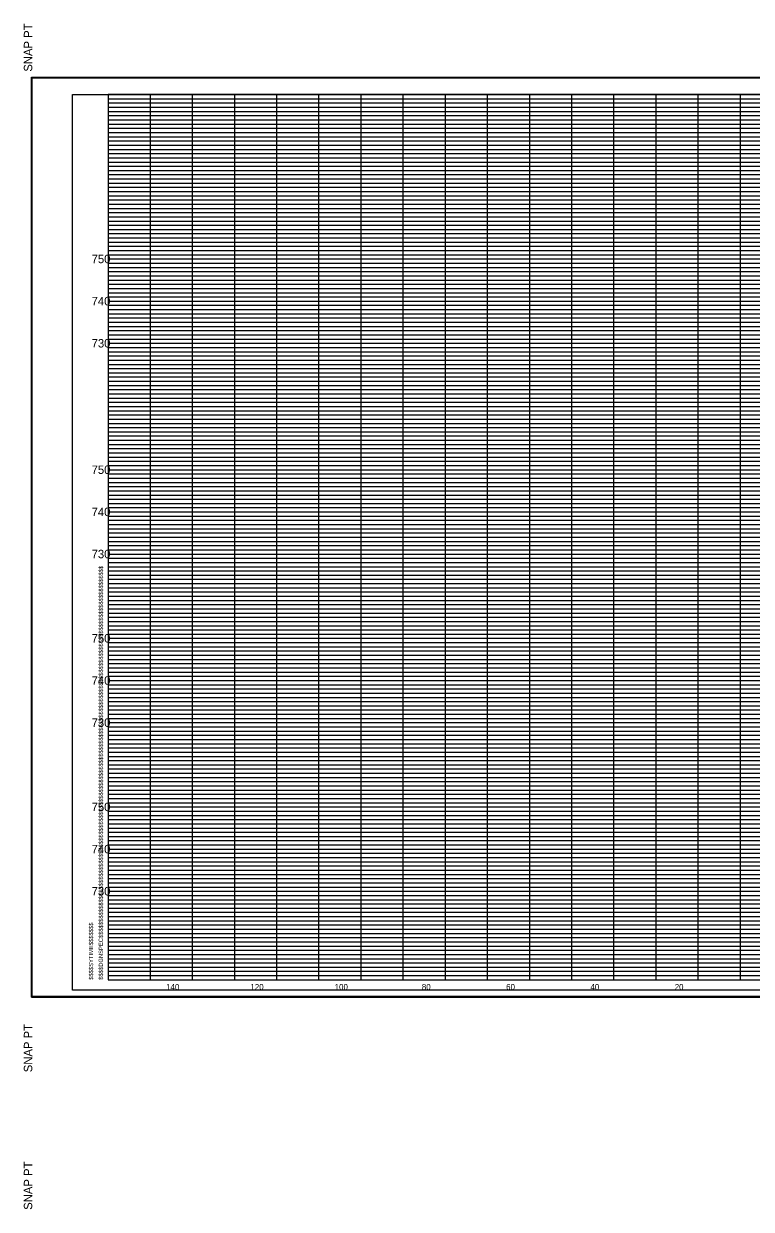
# Model space of a CAD drawing. Extents: x -200 to 1704, y -325 to 2307.
# Drawn here: x 979.9 to 1152.6, y 2025.5 to 2306.8 of the extents above; entities that cross this region are included whole.
import ezdxf

# ---------------------------------------------------------------- set-up
doc = ezdxf.new("R2010")
doc.units = 0
for name, color, linetype in [('DESIGN - SHEET - Corner Text', 7, 'Continuous'), ('DESIGN - SHEET - Light Grid', 7, 'Continuous'), ('DESIGN - SHEET - Linework', 7, 'Continuous'), ('DESIGN - SHEET - Plot Shape', 7, 'Continuous'), ('DESIGN - TYPICAL - Text', 7, 'Continuous')]:
    doc.layers.add(name, color=color, linetype=linetype)

msp = doc.modelspace()

# ---------------------------------------------------------------- linework, layer by layer
at = {"layer": 'DESIGN - SHEET - Light Grid'}
for p, q in [((1000, 2289), (1080, 2289)), ((1000, 2288), (1080, 2288)), ((1000, 2287), (1080, 2287)), ((1080, 2289), (1160, 2289)), ((1080, 2288), (1160, 2288)), ((1080, 2287), (1160, 2287)), ((1000, 2286), (1080, 2286)), ((1000, 2285), (1080, 2285)), ((1000, 2284), (1080, 2284)), ((1080, 2286), (1160, 2286)), ((1080, 2285), (1160, 2285)), ((1080, 2284), (1160, 2284)), ((1000, 2283), (1080, 2283)), ((1000, 2282), (1080, 2282)), ((1080, 2283), (1160, 2283)), ((1080, 2282), (1160, 2282)), ((1000, 2281), (1080, 2281)), ((1000, 2279), (1080, 2279)), ((1080, 2281), (1160, 2281)), ((1080, 2279), (1160, 2279)), ((1000, 2278), (1080, 2278)), ((1000, 2277), (1080, 2277)), ((1000, 2276), (1080, 2276)), ((1080, 2278), (1160, 2278)), ((1080, 2277), (1160, 2277)), ((1080, 2276), (1160, 2276)), ((1000, 2275), (1080, 2275)), ((1000, 2274), (1080, 2274)), ((1000, 2273), (1080, 2273)), ((1080, 2275), (1160, 2275)), ((1080, 2274), (1160, 2274)), ((1080, 2273), (1160, 2273)), ((1000, 2272), (1080, 2272)), ((1000, 2271), (1080, 2271)), ((1080, 2272), (1160, 2272)), ((1080, 2271), (1160, 2271)), ((1000, 2269), (1080, 2269)), ((1000, 2268), (1080, 2268)), ((1000, 2267), (1080, 2267)), ((1080, 2269), (1160, 2269)), ((1080, 2268), (1160, 2268)), ((1080, 2267), (1160, 2267)), ((1000, 2266), (1080, 2266)), ((1000, 2265), (1080, 2265)), ((1080, 2266), (1160, 2266)), ((1080, 2265), (1160, 2265)), ((1000, 2264), (1080, 2264)), ((1000, 2263), (1080, 2263)), ((1000, 2262), (1080, 2262)), ((1080, 2264), (1160, 2264)), ((1080, 2263), (1160, 2263)), ((1080, 2262), (1160, 2262)), ((1000, 2261), (1080, 2261)), ((1000, 2259), (1080, 2259)), ((1080, 2261), (1160, 2261)), ((1080, 2259), (1160, 2259)), ((1000, 2258), (1080, 2258)), ((1000, 2257), (1080, 2257)), ((1000, 2256), (1080, 2256)), ((1080, 2258), (1160, 2258)), ((1080, 2257), (1160, 2257)), ((1080, 2256), (1160, 2256)), ((1000, 2255), (1080, 2255)), ((1000, 2254), (1080, 2254)), ((1000, 2253), (1080, 2253)), ((1080, 2255), (1160, 2255)), ((1080, 2254), (1160, 2254)), ((1080, 2253), (1160, 2253)), ((1000, 2252), (1080, 2252)), ((1000, 2251), (1080, 2251)), ((1080, 2252), (1160, 2252)), ((1080, 2251), (1160, 2251)), ((1000, 2249), (1080, 2249)), ((1000, 2248), (1080, 2248)), ((1080, 2249), (1160, 2249)), ((1080, 2248), (1160, 2248)), ((1000, 2247), (1080, 2247)), ((1000, 2246), (1080, 2246)), ((1000, 2245), (1080, 2245)), ((1080, 2247), (1160, 2247)), ((1080, 2246), (1160, 2246)), ((1080, 2245), (1160, 2245)), ((1000, 2244), (1080, 2244)), ((1000, 2243), (1080, 2243)), ((1000, 2242), (1080, 2242)), ((1080, 2244), (1160, 2244)), ((1080, 2243), (1160, 2243)), ((1080, 2242), (1160, 2242)), ((1000, 2241), (1080, 2241)), ((1000, 2239), (1080, 2239)), ((1080, 2241), (1160, 2241)), ((1080, 2239), (1160, 2239)), ((1000, 2238), (1080, 2238)), ((1000, 2237), (1080, 2237)), ((1080, 2238), (1160, 2238)), ((1080, 2237), (1160, 2237)), ((1000, 2236), (1080, 2236)), ((1000, 2235), (1080, 2235)), ((1000, 2234), (1080, 2234)), ((1080, 2236), (1160, 2236)), ((1080, 2235), (1160, 2235)), ((1080, 2234), (1160, 2234)), ((1000, 2233), (1080, 2233)), ((1000, 2232), (1080, 2232)), ((1000, 2231), (1080, 2231)), ((1080, 2233), (1160, 2233)), ((1080, 2232), (1160, 2232)), ((1080, 2231), (1160, 2231)), ((1000, 2229), (1080, 2229)), ((1000, 2228), (1080, 2228)), ((1080, 2229), (1160, 2229)), ((1080, 2228), (1160, 2228)), ((1000, 2227), (1080, 2227)), ((1000, 2226), (1080, 2226)), ((1000, 2225), (1080, 2225)), ((1080, 2227), (1160, 2227)), ((1080, 2226), (1160, 2226)), ((1080, 2225), (1160, 2225)), ((1000, 2224), (1080, 2224)), ((1000, 2223), (1080, 2223)), ((1000, 2222), (1080, 2222)), ((1080, 2224), (1160, 2224)), ((1080, 2223), (1160, 2223)), ((1080, 2222), (1160, 2222)), ((1000, 2221), (1080, 2221)), ((1080, 2221), (1160, 2221)), ((1000, 2219), (1080, 2219)), ((1000, 2218), (1080, 2218)), ((1000, 2217), (1080, 2217)), ((1080, 2219), (1160, 2219)), ((1080, 2218), (1160, 2218)), ((1080, 2217), (1160, 2217)), ((1000, 2216), (1080, 2216)), ((1000, 2215), (1080, 2215)), ((1000, 2214), (1080, 2214)), ((1080, 2216), (1160, 2216)), ((1080, 2215), (1160, 2215)), ((1080, 2214), (1160, 2214)), ((1000, 2213), (1080, 2213)), ((1000, 2212), (1080, 2212)), ((1000, 2211), (1080, 2211)), ((1080, 2213), (1160, 2213)), ((1080, 2212), (1160, 2212)), ((1080, 2211), (1160, 2211)), ((1000, 2209), (1080, 2209)), ((1000, 2208), (1080, 2208)), ((1080, 2209), (1160, 2209)), ((1080, 2208), (1160, 2208)), ((1000, 2207), (1080, 2207)), ((1000, 2206), (1080, 2206)), ((1080, 2207), (1160, 2207)), ((1080, 2206), (1160, 2206)), ((1000, 2205), (1080, 2205)), ((1000, 2204), (1080, 2204)), ((1000, 2203), (1080, 2203)), ((1080, 2205), (1160, 2205)), ((1080, 2204), (1160, 2204)), ((1080, 2203), (1160, 2203)), ((1000, 2202), (1080, 2202)), ((1000, 2201), (1080, 2201)), ((1080, 2202), (1160, 2202)), ((1080, 2201), (1160, 2201)), ((1000, 2199), (1080, 2199)), ((1000, 2198), (1080, 2198)), ((1000, 2197), (1080, 2197)), ((1080, 2199), (1160, 2199)), ((1080, 2198), (1160, 2198)), ((1080, 2197), (1160, 2197)), ((1000, 2196), (1080, 2196)), ((1000, 2195), (1080, 2195)), ((1000, 2194), (1080, 2194)), ((1080, 2196), (1160, 2196)), ((1080, 2195), (1160, 2195)), ((1080, 2194), (1160, 2194)), ((1000, 2193), (1080, 2193)), ((1000, 2192), (1080, 2192)), ((1080, 2193), (1160, 2193)), ((1080, 2192), (1160, 2192)), ((1000, 2191), (1080, 2191)), ((1000, 2189), (1080, 2189)), ((1080, 2191), (1160, 2191)), ((1080, 2189), (1160, 2189)), ((1000, 2188), (1080, 2188)), ((1000, 2187), (1080, 2187)), ((1000, 2186), (1080, 2186)), ((1080, 2188), (1160, 2188)), ((1080, 2187), (1160, 2187)), ((1080, 2186), (1160, 2186)), ((1000, 2185), (1080, 2185)), ((1000, 2184), (1080, 2184)), ((1000, 2183), (1080, 2183)), ((1080, 2185), (1160, 2185)), ((1080, 2184), (1160, 2184)), ((1080, 2183), (1160, 2183)), ((1000, 2182), (1080, 2182)), ((1000, 2181), (1080, 2181)), ((1080, 2182), (1160, 2182)), ((1080, 2181), (1160, 2181)), ((1000, 2179), (1080, 2179)), ((1000, 2178), (1080, 2178)), ((1000, 2177), (1080, 2177)), ((1080, 2179), (1160, 2179)), ((1080, 2178), (1160, 2178)), ((1080, 2177), (1160, 2177)), ((1000, 2176), (1080, 2176)), ((1000, 2175), (1080, 2175)), ((1080, 2176), (1160, 2176)), ((1080, 2175), (1160, 2175)), ((1000, 2174), (1080, 2174)), ((1000, 2173), (1080, 2173)), ((1000, 2172), (1080, 2172)), ((1080, 2174), (1160, 2174)), ((1080, 2173), (1160, 2173)), ((1080, 2172), (1160, 2172)), ((1000, 2171), (1080, 2171)), ((1000, 2169), (1080, 2169)), ((1080, 2171), (1160, 2171)), ((1080, 2169), (1160, 2169)), ((1000, 2168), (1080, 2168)), ((1000, 2167), (1080, 2167)), ((1000, 2166), (1080, 2166)), ((1080, 2168), (1160, 2168)), ((1080, 2167), (1160, 2167)), ((1080, 2166), (1160, 2166)), ((1000, 2165), (1080, 2165)), ((1000, 2164), (1080, 2164)), ((1000, 2163), (1080, 2163)), ((1080, 2165), (1160, 2165)), ((1080, 2164), (1160, 2164)), ((1080, 2163), (1160, 2163)), ((1000, 2162), (1080, 2162)), ((1000, 2161), (1080, 2161)), ((1080, 2162), (1160, 2162)), ((1080, 2161), (1160, 2161)), ((1000, 2159), (1080, 2159)), ((1000, 2158), (1080, 2158)), ((1080, 2159), (1160, 2159)), ((1080, 2158), (1160, 2158)), ((1000, 2157), (1080, 2157)), ((1000, 2156), (1080, 2156)), ((1000, 2155), (1080, 2155)), ((1080, 2157), (1160, 2157)), ((1080, 2156), (1160, 2156)), ((1080, 2155), (1160, 2155)), ((1000, 2154), (1080, 2154)), ((1000, 2153), (1080, 2153)), ((1000, 2152), (1080, 2152)), ((1080, 2154), (1160, 2154)), ((1080, 2153), (1160, 2153)), ((1080, 2152), (1160, 2152)), ((1000, 2151), (1080, 2151)), ((1000, 2149), (1080, 2149)), ((1080, 2151), (1160, 2151)), ((1080, 2149), (1160, 2149)), ((1000, 2148), (1080, 2148)), ((1000, 2147), (1080, 2147)), ((1080, 2148), (1160, 2148)), ((1080, 2147), (1160, 2147)), ((1000, 2146), (1080, 2146)), ((1000, 2145), (1080, 2145)), ((1000, 2144), (1080, 2144)), ((1080, 2146), (1160, 2146)), ((1080, 2145), (1160, 2145)), ((1080, 2144), (1160, 2144)), ((1000, 2143), (1080, 2143)), ((1000, 2142), (1080, 2142)), ((1000, 2141), (1080, 2141)), ((1080, 2143), (1160, 2143)), ((1080, 2142), (1160, 2142)), ((1080, 2141), (1160, 2141)), ((1000, 2139), (1080, 2139)), ((1000, 2138), (1080, 2138)), ((1080, 2139), (1160, 2139)), ((1080, 2138), (1160, 2138)), ((1000, 2137), (1080, 2137)), ((1000, 2136), (1080, 2136)), ((1000, 2135), (1080, 2135)), ((1080, 2137), (1160, 2137)), ((1080, 2136), (1160, 2136)), ((1080, 2135), (1160, 2135)), ((1000, 2134), (1080, 2134)), ((1000, 2133), (1080, 2133)), ((1000, 2132), (1080, 2132)), ((1080, 2134), (1160, 2134)), ((1080, 2133), (1160, 2133)), ((1080, 2132), (1160, 2132)), ((1000, 2131), (1080, 2131)), ((1080, 2131), (1160, 2131)), ((1000, 2129), (1080, 2129)), ((1000, 2128), (1080, 2128)), ((1000, 2127), (1080, 2127)), ((1080, 2129), (1160, 2129)), ((1080, 2128), (1160, 2128)), ((1080, 2127), (1160, 2127)), ((1000, 2126), (1080, 2126)), ((1000, 2125), (1080, 2125)), ((1000, 2124), (1080, 2124)), ((1080, 2126), (1160, 2126)), ((1080, 2125), (1160, 2125)), ((1080, 2124), (1160, 2124)), ((1000, 2123), (1080, 2123)), ((1000, 2122), (1080, 2122)), ((1000, 2121), (1080, 2121)), ((1080, 2123), (1160, 2123)), ((1080, 2122), (1160, 2122)), ((1080, 2121), (1160, 2121)), ((1000, 2119), (1080, 2119)), ((1000, 2118), (1080, 2118)), ((1080, 2119), (1160, 2119)), ((1080, 2118), (1160, 2118)), ((1000, 2117), (1080, 2117)), ((1000, 2116), (1080, 2116)), ((1080, 2117), (1160, 2117)), ((1080, 2116), (1160, 2116)), ((1000, 2115), (1080, 2115)), ((1000, 2114), (1080, 2114)), ((1000, 2113), (1080, 2113)), ((1080, 2115), (1160, 2115)), ((1080, 2114), (1160, 2114)), ((1080, 2113), (1160, 2113)), ((1000, 2112), (1080, 2112)), ((1000, 2111), (1080, 2111)), ((1080, 2112), (1160, 2112)), ((1080, 2111), (1160, 2111)), ((1000, 2109), (1080, 2109)), ((1000, 2108), (1080, 2108)), ((1000, 2107), (1080, 2107)), ((1080, 2109), (1160, 2109)), ((1080, 2108), (1160, 2108)), ((1080, 2107), (1160, 2107)), ((1000, 2106), (1080, 2106)), ((1000, 2105), (1080, 2105)), ((1000, 2104), (1080, 2104)), ((1080, 2106), (1160, 2106)), ((1080, 2105), (1160, 2105)), ((1080, 2104), (1160, 2104)), ((1000, 2103), (1080, 2103)), ((1000, 2102), (1080, 2102)), ((1080, 2103), (1160, 2103)), ((1080, 2102), (1160, 2102)), ((1000, 2101), (1080, 2101)), ((1000, 2099), (1080, 2099)), ((1080, 2101), (1160, 2101)), ((1080, 2099), (1160, 2099)), ((1000, 2098), (1080, 2098)), ((1000, 2097), (1080, 2097)), ((1000, 2096), (1080, 2096)), ((1080, 2098), (1160, 2098)), ((1080, 2097), (1160, 2097)), ((1080, 2096), (1160, 2096)), ((1000, 2095), (1080, 2095)), ((1000, 2094), (1080, 2094)), ((1000, 2093), (1080, 2093)), ((1080, 2095), (1160, 2095)), ((1080, 2094), (1160, 2094)), ((1080, 2093), (1160, 2093)), ((1000, 2092), (1080, 2092)), ((1000, 2091), (1080, 2091)), ((1080, 2092), (1160, 2092)), ((1080, 2091), (1160, 2091)), ((1000, 2089), (1080, 2089)), ((1000, 2088), (1080, 2088)), ((1000, 2087), (1080, 2087)), ((1080, 2089), (1160, 2089)), ((1080, 2088), (1160, 2088)), ((1080, 2087), (1160, 2087)), ((1000, 2086), (1080, 2086)), ((1000, 2085), (1080, 2085)), ((1080, 2086), (1160, 2086)), ((1080, 2085), (1160, 2085)), ((1000, 2084), (1080, 2084)), ((1000, 2083), (1080, 2083)), ((1000, 2082), (1080, 2082)), ((1080, 2084), (1160, 2084)), ((1080, 2083), (1160, 2083)), ((1080, 2082), (1160, 2082)), ((1000, 2081), (1080, 2081)), ((1080, 2081), (1160, 2081))]:
    msp.add_line(p, q, dxfattribs=at)
at = {"layer": 'DESIGN - SHEET - Linework'}
for p, q in [((981.77, 2075.86), (981.77, 2294.14)), ((981.77, 2294.14), (1322.17, 2294.14)), ((1010, 2080), (1010, 2290)), ((1020, 2080), (1020, 2290)), ((1030, 2080), (1030, 2290)), ((1040, 2080), (1040, 2290)), ((1050, 2080), (1050, 2290)), ((1060, 2080), (1060, 2290)), ((1070, 2080), (1070, 2290)), ((1080, 2080), (1080, 2290)), ((1090, 2080), (1090, 2290)), ((1100, 2080), (1100, 2290)), ((1110, 2080), (1110, 2290)), ((1120, 2080), (1120, 2290)), ((1130, 2080), (1130, 2290)), ((1140, 2080), (1140, 2290)), ((1150, 2080), (1150, 2290)), ((1000, 2280), (1280, 2280)), ((1000, 2270), (1320, 2270)), ((1000, 2260), (1320, 2260)), ((1000, 2250), (1320, 2250)), ((1000, 2240), (1320, 2240)), ((1000, 2230), (1320, 2230)), ((1000, 2220), (1320, 2220)), ((1000, 2210), (1320, 2210)), ((1000, 2200), (1320, 2200)), ((1000, 2190), (1320, 2190)), ((1000, 2180), (1320, 2180)), ((1000, 2170), (1320, 2170)), ((1000, 2160), (1320, 2160)), ((1000, 2150), (1320, 2150)), ((1000, 2140), (1320, 2140)), ((1000, 2130), (1320, 2130)), ((1000, 2120), (1320, 2120)), ((1000, 2110), (1320, 2110)), ((1000, 2100), (1320, 2100)), ((1000, 2090), (1320, 2090)), ((981.77, 2075.86), (1322.17, 2075.86))]:
    msp.add_line(p, q, dxfattribs=at)
msp.add_lwpolyline([(1000, 2290), (1000, 2080), (1320, 2080), (1320, 2290), (1000, 2290)], dxfattribs=at)
at = {"layer": 'DESIGN - SHEET - Plot Shape'}
for points in [[(981.97, 2293.94), (1321.97, 2293.94), (1321.97, 2076.06), (981.97, 2076.06)], [(991.5, 2290), (1320, 2290), (1320, 2077.5), (991.5, 2077.5)]]:
    msp.add_lwpolyline(points, close=True, dxfattribs=at)

# ---------------------------------------------------------------- texts
at = {"layer": 'DESIGN - SHEET - Corner Text'}
for s, height, p in [('  SNAP PT', 2, (981.97, 2293.94)), ('$$$$DGNSPEC$$$$$$$$$$$$$$$$$$$$$$$$$$$$$$$$$$$$$$$$$$$$$$$$$$$$$$$$$$$$$$$$$$$$$$$$$$$$$$$$$$$$$$$$$$$$$$$$$$$$$$$$$$$$$$$$$$$', 1.00002, (998.74, 2080)), ('$$$$SYTIME$$$$$$$', 1, (996.42, 2080)), ('SNAP PT  ', 2, (981.97, 2058.06)), ('  SNAP PT', 2, (981.97, 2023.94))]:
    msp.add_text(s, height=height, rotation=90, dxfattribs=at).set_placement(p)
at = {"layer": 'DESIGN - TYPICAL - Text'}
for s, height, p in [('     750     ', 2, (992.34, 2250)), ('     740     ', 2, (992.34, 2240)), ('     730     ', 2, (992.34, 2230)), ('     750     ', 2, (992.34, 2200)), ('     740     ', 2, (992.34, 2190)), ('     730     ', 2, (992.34, 2180)), ('     750     ', 2, (992.34, 2160)), ('     740     ', 2, (992.34, 2150)), ('     730     ', 2, (992.34, 2140)), ('     750     ', 2, (992.34, 2120)), ('     740     ', 2, (992.34, 2110)), ('     730     ', 2, (992.34, 2100)), ('     140     ', 1.4, (1011.14, 2077.6)), ('     120     ', 1.4, (1031.14, 2077.6)), ('     100     ', 1.4, (1051.14, 2077.6)), ('     80     ', 1.4, (1071.82, 2077.6)), ('     60     ', 1.4, (1091.82, 2077.6)), ('     40     ', 1.4, (1111.82, 2077.6)), ('     20     ', 1.4, (1131.82, 2077.6))]:
    msp.add_text(s, height=height, dxfattribs=at).set_placement(p)

doc.saveas('drawing.dxf')
